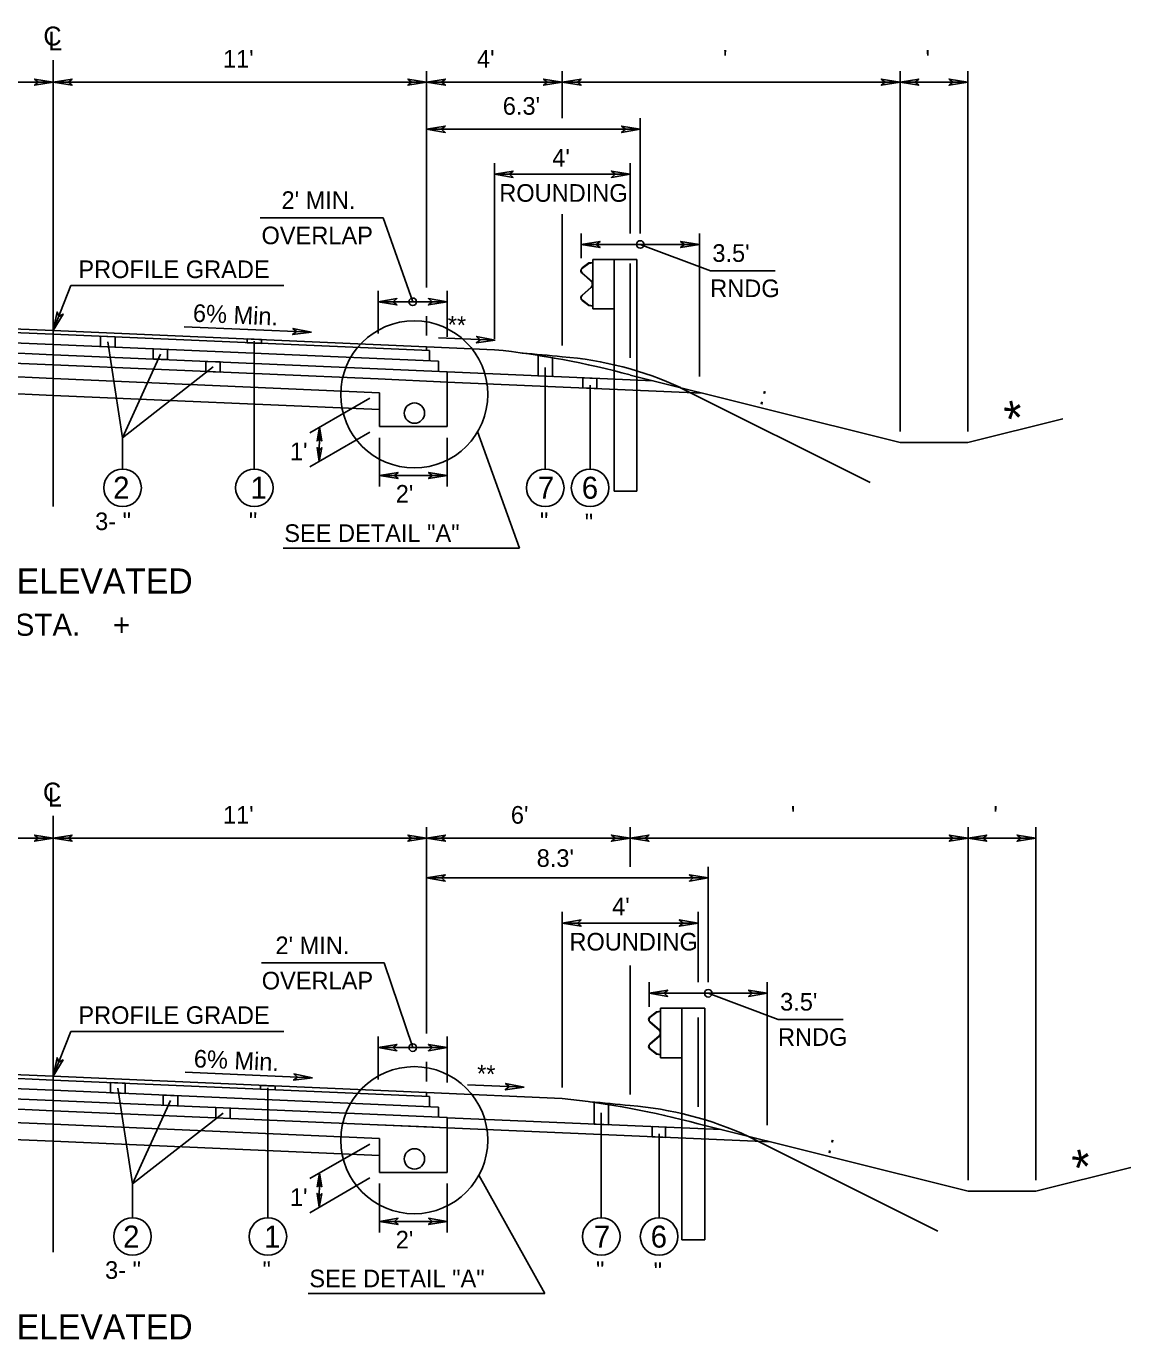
# Model space of a CAD drawing. Extents: x -540 to 1231, y -564 to 421.
# Drawn here: x 844.4 to 932.1, y 183.6 to 287.9 of the extents above; entities that cross this region are included whole.
import ezdxf

# ---------------------------------------------------------------- set-up
doc = ezdxf.new("R2010")
doc.units = 0
doc.layers.add('1', color=7, linetype='Continuous')
doc.layers.add('Des_ Drain_ Ftrs', color=7, linetype='Continuous')

msp = doc.modelspace()

# ---------------------------------------------------------------- linework, layer by layer
at = {"layer": '1'}
for p, q in [((846.54, 249.77), (846.54, 285.21)), ((876.18, 267.15), (876.18, 284.33)), ((886.95, 280.6), (886.95, 284.33)), ((913.77, 255.72), (913.77, 284.33)), ((919.16, 255.72), (919.16, 284.33)), ((846.54, 283.45), (816.91, 283.45)), ((846.54, 283.45), (876.18, 283.45)), ((876.18, 283.45), (886.95, 283.45)), ((886.95, 283.45), (913.77, 283.45)), ((913.77, 283.45), (919.16, 283.45)), ((893.15, 271.45), (893.15, 280.6)), ((876.18, 279.72), (893.15, 279.72)), ((881.57, 263.09), (881.57, 277.03)), ((892.34, 271.45), (892.34, 277.03)), ((881.57, 276.15), (892.34, 276.15)), ((862.97, 272.69), (872.74, 272.69)), ((875.08, 266.02), (872.74, 272.69)), ((886.95, 262.54), (886.95, 272.99)), ((888.46, 269.49), (888.46, 271.45)), ((897.84, 260.09), (897.84, 271.45)), ((888.46, 270.57), (897.84, 270.57)), ((893.15, 270.57), (898.71, 268.49)), ((889.06, 269.1), (888.54, 268.71)), ((889.37, 269.15), (889.06, 269.1)), ((889.37, 269.12), (889.07, 269.07)), ((889.37, 269.38), (889.37, 265.45)), ((889.37, 269.38), (891.06, 269.38)), ((891.06, 269.38), (891.06, 250.98)), ((892.88, 269.38), (891.06, 269.38)), ((892.88, 269.38), (892.88, 250.98)), ((888.52, 268.28), (889.25, 267.64)), ((888.54, 268.3), (889.27, 267.66)), ((889.07, 269.07), (888.56, 268.68)), ((892.34, 261.57), (892.34, 269.07)), ((898.71, 268.49), (903.86, 268.49)), ((846.54, 263.74), (847.92, 267.31)), ((864.84, 267.31), (847.92, 267.31)), ((889.25, 267.19), (888.52, 266.55)), ((889.27, 267.17), (888.54, 266.53)), ((889.34, 267.45), (889.34, 267.38)), ((889.37, 267.45), (889.37, 267.38)), ((872.33, 263.49), (872.33, 266.9)), ((872.33, 266.02), (877.82, 266.02)), ((877.82, 263.25), (877.82, 266.9)), ((888.54, 266.12), (889.06, 265.73)), ((888.56, 266.15), (889.07, 265.76)), ((846.54, 263.74), (816.9, 265.04)), ((889.06, 265.73), (889.37, 265.68)), ((889.07, 265.76), (889.37, 265.71)), ((889.37, 265.45), (891.06, 265.45)), ((846.54, 262.63), (815.64, 263.98)), ((846.54, 263.44), (816.56, 264.75)), ((856.93, 264.04), (867.04, 263.6)), ((876.18, 263.33), (876.18, 264.89)), ((846.54, 261.82), (814.72, 263.21)), ((876.18, 262.45), (846.54, 263.74)), ((876.42, 262.14), (846.54, 263.44)), ((850.87, 262.85), (852.04, 255.22)), ((862.5, 262.88), (862.5, 252.74)), ((881.62, 262.96), (877.13, 263.15)), ((846.54, 261.01), (814.73, 262.4)), ((877.12, 261.3), (846.54, 262.63)), ((877.82, 260.46), (846.54, 261.82)), ((855.05, 261.86), (852.04, 255.22)), ((881.57, 262.21), (876.18, 262.45)), ((876.18, 262.45), (876.18, 262.15)), ((876.42, 262.14), (876.42, 261.33)), ((846.54, 259.94), (820.1, 261.09)), ((872.34, 259.89), (846.54, 261.01)), ((859.22, 260.85), (852.04, 255.22)), ((877.12, 261.3), (877.12, 260.49)), ((885.6, 260.79), (885.6, 252.74)), ((888.46, 261.43), (888.46, 261.43)), ((846.54, 258.59), (820.1, 259.74)), ((872.44, 258.8), (846.54, 259.94)), ((877.82, 259.65), (872.34, 259.89)), ((877.84, 259.65), (876.18, 259.72)), ((877.82, 260.46), (877.82, 259.65)), ((894.17, 259.74), (877.82, 260.46)), ((892.34, 260.2), (913.77, 254.84)), ((872.44, 256.11), (872.44, 258.8)), ((872.44, 258.8), (872.44, 258.8)), ((877.82, 256.11), (877.82, 259.65)), ((898.09, 258.76), (877.82, 259.65)), ((889.16, 259.39), (889.16, 252.74)), ((896.34, 259.2), (911.39, 251.68)), ((872.44, 257.46), (846.54, 258.59)), ((871.67, 258.36), (866.92, 255.62)), ((926.69, 256.73), (919.16, 254.84)), ((871.67, 255.67), (866.9, 252.91)), ((867.68, 256.06), (867.66, 253.35)), ((872.44, 256.11), (877.82, 256.11)), ((880.23, 255.71), (883.56, 246.45)), ((852.04, 255.22), (852.04, 252.74)), ((872.44, 255.23), (872.44, 251.34)), ((877.82, 255.23), (877.82, 251.34)), ((913.77, 254.84), (919.16, 254.84)), ((872.44, 252.22), (877.82, 252.22)), ((892.88, 250.98), (891.06, 250.98)), ((864.78, 246.45), (883.56, 246.45)), ((846.54, 190.55), (846.54, 225.19)), ((876.18, 207.93), (876.18, 224.31)), ((892.34, 221.15), (892.34, 224.31)), ((919.17, 196.27), (919.17, 224.31)), ((924.55, 196.27), (924.55, 224.31)), ((846.54, 223.43), (816.91, 223.43)), ((846.54, 223.43), (876.18, 223.43)), ((876.18, 223.43), (892.34, 223.43)), ((892.34, 223.43), (919.17, 223.43)), ((919.17, 223.43), (924.55, 223.43)), ((898.54, 211.99), (898.54, 221.15)), ((876.18, 220.27), (898.54, 220.27)), ((886.95, 203.63), (886.95, 217.57)), ((897.73, 211.99), (897.73, 217.57)), ((886.95, 216.69), (897.73, 216.69)), ((863.06, 213.52), (872.82, 213.52)), ((875.08, 206.8), (872.82, 213.52)), ((892.34, 203.08), (892.34, 213.33)), ((893.85, 210.04), (893.85, 211.99)), ((903.23, 200.64), (903.23, 211.99)), ((893.85, 211.11), (903.23, 211.11)), ((898.54, 211.11), (904.09, 209.04)), ((894.44, 209.64), (893.93, 209.25)), ((894.76, 209.7), (894.44, 209.64)), ((894.76, 209.67), (894.46, 209.61)), ((894.76, 209.93), (894.76, 205.99)), ((894.76, 209.93), (896.44, 209.93)), ((896.44, 209.93), (896.44, 191.53)), ((898.27, 209.93), (896.44, 209.93)), ((898.27, 209.93), (898.27, 191.53)), ((893.91, 208.82), (894.64, 208.18)), ((893.93, 208.84), (894.66, 208.21)), ((894.46, 209.61), (893.94, 209.23)), ((897.73, 202.11), (897.73, 209.19)), ((904.09, 209.04), (909.25, 209.04)), ((846.54, 204.52), (847.92, 208.09)), ((864.84, 208.09), (847.92, 208.09)), ((872.33, 204.27), (872.33, 207.68)), ((877.82, 204.03), (877.82, 207.68)), ((894.64, 207.73), (893.91, 207.1)), ((894.66, 207.71), (893.93, 207.08)), ((894.73, 208), (894.73, 207.92)), ((894.76, 208), (894.76, 207.92)), ((872.33, 206.8), (877.82, 206.8)), ((893.93, 206.67), (894.44, 206.28)), ((893.94, 206.69), (894.46, 206.3)), ((846.54, 204.22), (816.56, 205.53)), ((846.54, 204.52), (816.9, 205.82)), ((876.18, 204.11), (876.18, 205.67)), ((894.44, 206.28), (894.76, 206.22)), ((894.46, 206.3), (894.76, 206.25)), ((894.76, 205.99), (896.44, 205.99)), ((846.54, 203.41), (815.64, 204.76)), ((876.18, 203.23), (846.54, 204.52)), ((857, 204.84), (867.12, 204.4)), ((846.54, 202.6), (814.72, 203.99)), ((876.42, 202.92), (846.54, 204.22)), ((877.12, 202.08), (846.54, 203.41)), ((851.67, 203.59), (852.83, 195.97)), ((863.58, 203.6), (863.58, 193.28)), ((883.92, 203.65), (879.43, 203.84)), ((846.54, 201.79), (814.72, 203.18)), ((877.82, 201.24), (846.54, 202.6)), ((855.84, 202.61), (852.83, 195.97)), ((886.95, 202.75), (876.18, 203.23)), ((876.18, 203.23), (876.18, 202.93)), ((876.42, 202.92), (876.42, 202.11)), ((846.54, 200.71), (820.1, 201.87)), ((877.82, 200.43), (846.54, 201.79)), ((860.02, 201.59), (852.83, 195.97)), ((877.12, 202.08), (877.12, 201.27)), ((890.05, 201.62), (890.05, 193.28)), ((893.85, 201.98), (893.85, 201.98)), ((846.54, 199.37), (820.1, 200.52)), ((872.44, 199.58), (846.54, 200.71)), ((876.18, 200.5), (872.34, 200.67)), ((877.82, 200.43), (876.17, 200.5)), ((877.82, 201.24), (877.82, 200.43)), ((877.82, 196.89), (877.82, 200.43)), ((903.48, 199.31), (877.82, 200.43)), ((899.57, 200.29), (877.84, 201.23)), ((897.73, 200.75), (919.17, 195.39)), ((872.44, 198.24), (846.54, 199.37)), ((872.44, 196.89), (872.44, 199.58)), ((872.44, 199.58), (872.44, 199.58)), ((894.64, 199.94), (894.64, 193.28)), ((901.73, 199.75), (916.78, 192.22)), ((871.67, 199.14), (866.92, 196.4)), ((932.09, 197.27), (924.55, 195.39)), ((871.67, 196.45), (866.9, 193.69)), ((867.68, 196.84), (867.66, 194.13)), ((872.44, 196.89), (877.82, 196.89)), ((880.33, 196.66), (885.56, 187.27)), ((852.83, 195.97), (852.83, 193.28)), ((872.44, 196.01), (872.44, 192.12)), ((877.82, 196.01), (877.82, 192.12)), ((919.17, 195.39), (924.55, 195.39)), ((872.44, 193), (877.82, 193)), ((898.27, 191.53), (896.44, 191.53)), ((866.77, 187.27), (885.56, 187.27))]:
    msp.add_line(p, q, dxfattribs=at)
for points in [[(850.3, 263.28), (851.45, 263.23), (851.45, 262.42), (850.3, 262.47)], [(861.93, 263.07), (863.07, 263.02), (863.07, 262.72), (861.93, 262.77)], [(854.47, 262.29), (855.62, 262.24), (855.62, 261.43), (854.47, 261.48)], [(858.65, 261.29), (859.8, 261.24), (859.8, 260.44), (858.65, 260.49)], [(885.03, 261.76), (886.18, 261.57), (886.18, 260.09), (885.03, 260.14)], [(888.59, 259.99), (889.69, 259.94), (889.69, 259.13), (888.59, 259.18)], [(851.09, 204.02), (852.24, 203.97), (852.24, 203.16), (851.09, 203.21)], [(863, 203.8), (864.15, 203.75), (864.15, 203.45), (863, 203.5)], [(855.27, 203.03), (856.42, 202.98), (856.42, 202.17), (855.27, 202.22)], [(889.48, 202.45), (890.62, 202.27), (890.62, 200.68), (889.48, 200.73)], [(859.45, 202.04), (860.59, 201.99), (860.59, 201.18), (859.45, 201.23)], [(894.09, 200.53), (895.14, 200.48), (895.14, 199.67), (894.09, 199.72)]]:
    msp.add_lwpolyline(points, close=True, dxfattribs=at)
for centre, radius in [((893.15, 270.57), 0.3), ((875.08, 266.02), 0.3), ((875.2, 258.67), 5.84), ((875.21, 257.18), 0.808), ((852.04, 251.25), 1.49), ((862.5, 251.25), 1.49), ((885.6, 251.25), 1.49), ((889.16, 251.25), 1.49), ((898.54, 211.11), 0.3), ((875.08, 206.8), 0.3), ((875.2, 199.45), 5.84), ((875.21, 197.96), 0.808), ((852.83, 191.8), 1.49), ((863.58, 191.8), 1.49), ((890.05, 191.8), 1.49), ((894.64, 191.8), 1.49)]:
    msp.add_circle(centre, radius, dxfattribs=at)
for centre, radius, start, end in [((888.71, 268.49), 0.278, 126.9799, 229.021), ((888.71, 268.49), 0.249, 126.9799, 229.021), ((889.09, 267.45), 0.249, 0, 49.0365), ((889.09, 267.38), 0.249, 310.9635, 0), ((889.09, 267.45), 0.278, 0, 49.0365), ((889.09, 267.38), 0.278, 310.9635, 0), ((888.71, 266.34), 0.278, 130.979, 233.0201), ((888.71, 266.34), 0.249, 130.979, 233.0201), ((874.68, 195.38), 67.19, 74.7593, 84.1179), ((876.13, 160.99), 101.24, 83.8633, 85.6775), ((884.83, 234.37), 27.37, 65.1374, 85.5513), ((894.09, 209.03), 0.278, 126.9799, 229.021), ((894.09, 209.03), 0.249, 126.9799, 229.021), ((894.48, 208), 0.249, 0, 49.0365), ((894.48, 207.92), 0.249, 310.9635, 0), ((894.48, 208), 0.278, 0, 49.0365), ((894.48, 207.92), 0.278, 310.9635, 0), ((894.09, 206.89), 0.278, 130.979, 233.0201), ((894.09, 206.89), 0.249, 130.979, 233.0201), ((880.07, 135.92), 67.19, 74.7602, 84.1188), ((881.52, 101.54), 101.24, 83.8633, 85.6775), ((890.22, 174.91), 27.37, 65.1374, 85.5513)]:
    msp.add_arc(centre, radius, start, end, dxfattribs=at)
at = {"layer": 'Des_ Drain_ Ftrs'}
for points in [[(846.54, 283.45), (845.05, 283.21), (845.35, 283.45), (845.05, 283.7)], [(846.54, 283.45), (848.03, 283.21), (847.74, 283.45), (848.03, 283.7)], [(876.18, 283.45), (874.69, 283.21), (874.98, 283.45), (874.69, 283.7)], [(876.18, 283.45), (877.67, 283.21), (877.37, 283.45), (877.67, 283.7)], [(886.95, 283.45), (885.47, 283.21), (885.76, 283.45), (885.47, 283.7)], [(886.95, 283.45), (888.44, 283.21), (888.15, 283.45), (888.44, 283.7)], [(913.77, 283.45), (912.28, 283.21), (912.58, 283.45), (912.28, 283.7)], [(913.77, 283.45), (915.26, 283.21), (914.96, 283.45), (915.26, 283.7)], [(919.16, 283.45), (917.67, 283.21), (917.96, 283.45), (917.67, 283.7)], [(876.18, 279.72), (877.66, 279.47), (877.37, 279.72), (877.66, 279.97)], [(893.15, 279.72), (891.66, 279.47), (891.96, 279.72), (891.66, 279.97)], [(881.57, 276.15), (883.05, 275.9), (882.76, 276.15), (883.05, 276.4)], [(892.34, 276.15), (890.85, 275.9), (891.15, 276.15), (890.85, 276.4)], [(888.46, 270.57), (889.95, 270.32), (889.65, 270.57), (889.95, 270.81)], [(897.84, 270.57), (896.35, 270.32), (896.65, 270.57), (896.35, 270.81)], [(872.33, 266.02), (873.82, 265.77), (873.53, 266.02), (873.82, 266.27)], [(877.82, 266.02), (876.33, 265.77), (876.63, 266.02), (876.33, 266.27)], [(846.54, 263.74), (847.31, 265.04), (846.97, 264.86), (846.84, 265.22)], [(867.04, 263.6), (865.54, 263.41), (865.85, 263.65), (865.56, 263.91)], [(881.62, 262.96), (880.13, 262.77), (880.43, 263.01), (880.15, 263.27)], [(867.68, 256.06), (867.49, 254.97), (867.67, 255.19), (867.85, 254.97)], [(867.66, 253.35), (867.49, 254.44), (867.66, 254.22), (867.85, 254.44)], [(872.44, 252.22), (873.92, 251.98), (873.63, 252.22), (873.92, 252.47)], [(877.82, 252.22), (876.34, 251.98), (876.63, 252.22), (876.34, 252.47)], [(846.54, 223.43), (845.05, 223.18), (845.35, 223.43), (845.05, 223.68)], [(846.54, 223.43), (848.03, 223.18), (847.74, 223.43), (848.03, 223.68)], [(876.18, 223.43), (874.69, 223.18), (874.98, 223.43), (874.69, 223.68)], [(876.18, 223.43), (877.67, 223.18), (877.37, 223.43), (877.67, 223.68)], [(892.34, 223.43), (890.85, 223.18), (891.15, 223.43), (890.85, 223.68)], [(892.34, 223.43), (893.83, 223.18), (893.54, 223.43), (893.83, 223.68)], [(919.17, 223.43), (917.68, 223.18), (917.97, 223.43), (917.68, 223.68)], [(919.17, 223.43), (920.65, 223.18), (920.36, 223.43), (920.65, 223.68)], [(924.55, 223.43), (923.07, 223.18), (923.36, 223.43), (923.07, 223.68)], [(876.18, 220.27), (877.66, 220.02), (877.37, 220.27), (877.66, 220.51)], [(898.54, 220.27), (897.05, 220.02), (897.34, 220.27), (897.05, 220.51)], [(886.95, 216.69), (888.44, 216.44), (888.15, 216.69), (888.44, 216.94)], [(897.73, 216.69), (896.24, 216.44), (896.54, 216.69), (896.24, 216.94)], [(893.85, 211.11), (895.33, 210.86), (895.04, 211.11), (895.33, 211.36)], [(903.23, 211.11), (901.74, 210.86), (902.04, 211.11), (901.74, 211.36)], [(872.33, 206.8), (873.82, 206.55), (873.53, 206.8), (873.82, 207.05)], [(877.82, 206.8), (876.33, 206.55), (876.63, 206.8), (876.33, 207.05)], [(846.54, 204.52), (847.31, 205.82), (846.97, 205.64), (846.84, 206)], [(867.12, 204.4), (865.62, 204.22), (865.93, 204.45), (865.64, 204.71)], [(883.92, 203.65), (882.43, 203.46), (882.73, 203.7), (882.45, 203.96)], [(867.68, 196.84), (867.49, 195.75), (867.67, 195.97), (867.85, 195.75)], [(867.66, 194.13), (867.49, 195.22), (867.66, 195), (867.85, 195.21)], [(872.44, 193), (873.92, 192.76), (873.63, 193), (873.92, 193.25)], [(877.82, 193), (876.34, 192.76), (876.63, 193), (876.34, 193.25)]]:
    msp.add_lwpolyline(points, close=True, dxfattribs=at)

# ---------------------------------------------------------------- texts
at = {"layer": '1'}
for s, height, p in [("11'", 1.4, (860.01, 284.61)), ("4'", 1.4, (880.18, 284.61)), ("  '", 1.4, (898.67, 284.61)), (" '", 1.4, (915.27, 284.61)), ("6.3'", 1.4, (882.23, 280.87)), ("4'", 1.4, (886.16, 276.76)), ('ROUNDING', 1.4, (881.95, 273.96)), ("2' MIN.", 1.4, (864.66, 273.39)), ('OVERLAP', 1.4, (863.07, 270.59)), ("3.5'", 1.4, (898.87, 269.19)), ('PROFILE GRADE', 1.4, (848.53, 267.9)), ('RNDG', 1.4, (898.7, 266.39)), ('2', 1.75, (851.29, 250.38)), ('1', 1.75, (862.2, 250.38)), ("2'", 1.4, (873.73, 250.07)), ('7', 1.75, (885.01, 250.38)), ('6', 1.75, (888.5, 250.38)), ('3- "', 1.4, (849.86, 247.89)), (' "', 1.4, (861.55, 247.89)), (' "', 1.4, (884.66, 247.89)), ('SEE DETAIL "A"', 1.4, (864.88, 246.95)), (' "', 1.4, (888.22, 247.79)), ('SUPERELEVATED', 2, (834.42, 242.85)), ('STA.    +      TO STA.    +     ', 1.75, (826.51, 239.5)), ("11'", 1.4, (860.01, 224.58)), ("6'", 1.4, (882.87, 224.58)), ("  '", 1.4, (904.06, 224.58)), (" '", 1.4, (920.66, 224.58)), ("8.3'", 1.4, (884.92, 221.15)), ("4'", 1.4, (890.91, 217.31)), ('ROUNDING', 1.4, (887.52, 214.51)), ("2' MIN.", 1.4, (864.18, 214.22)), ('OVERLAP', 1.4, (863.09, 211.42)), ("3.5'", 1.4, (904.25, 209.74)), ('PROFILE GRADE', 1.4, (848.53, 208.68)), ('RNDG', 1.4, (904.08, 206.94)), ('2', 1.75, (852.08, 190.92)), ('1', 1.75, (863.27, 190.92)), ("2'", 1.4, (873.73, 190.85)), ('7', 1.75, (889.46, 190.92)), ('6', 1.75, (893.97, 190.92)), ('3- "', 1.4, (850.65, 188.44)), (' "', 1.4, (862.63, 188.44)), (' "', 1.4, (889.11, 188.44)), ('SEE DETAIL "A"', 1.4, (866.87, 187.77)), (' "', 1.4, (893.69, 188.34)), ('SUPERELEVATED', 2, (834.42, 183.63))]:
    msp.add_text(s, height=height, dxfattribs=at).set_placement(p)
for s, height, rotation, p in [('6% Min.', 1.4, 357.3731, (857.6, 264.44)), ('**', 1.4, 357.2169, (877.81, 263.52)), (' : ', 1.4, 345.7718, (902.01, 258.07)), ('*', 2.8, 12.8479, (922.47, 255.25)), ("1'", 1.4, 0.1438, (865.33, 253.44)), ('6% Min.', 1.4, 357.3727, (857.67, 205.24)), ('**', 1.4, 357.2168, (880.14, 204.05)), (' : ', 1.4, 345.7718, (907.4, 198.62)), ('*', 2.8, 12.8479, (927.87, 195.79)), ("1'", 1.4, 0.1438, (865.33, 194.22))]:
    msp.add_text(s, height=height, rotation=rotation, dxfattribs=at).set_placement(p)
at = {"layer": 'Des_ Drain_ Ftrs'}
for s, p in [('C', (845.75, 286.37)), ('L', (846.14, 285.98)), ('C', (845.72, 226.34)), ('L', (846.11, 225.94))]:
    msp.add_text(s, height=1.5, dxfattribs=at).set_placement(p)

doc.saveas('drawing.dxf')
